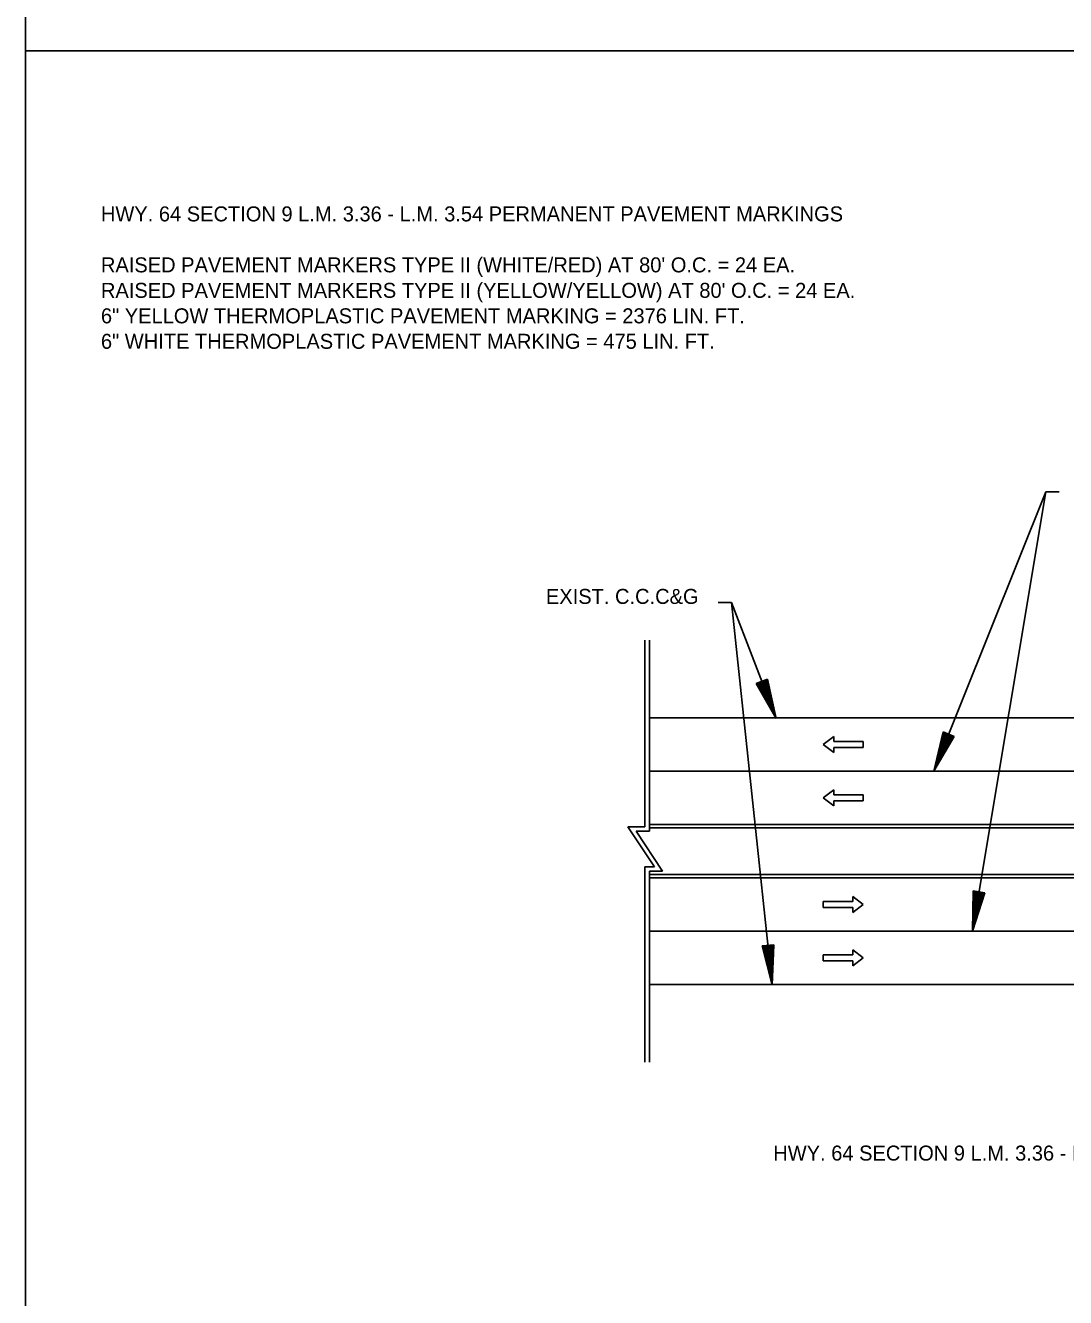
# Model space of a CAD drawing. Extents: x 1373096 to 1373266, y 381130 to 381790.
# Drawn here: x 1373096 to 1373174, y 381366.6 to 381462.1 of the extents above; entities that cross this region are included whole.
import ezdxf

# ---------------------------------------------------------------- set-up
doc = ezdxf.new("R2010")
doc.units = 0
for name, color, linetype in [('Default', 7, 'Continuous'), ('DSN_DRFT_Junk-No-Plot', 7, 'Continuous'), ('R_Draft', 7, 'Continuous')]:
    doc.layers.add(name, color=color, linetype=linetype)

msp = doc.modelspace()

# ---------------------------------------------------------------- linework, layer by layer
at = {"layer": 'Default'}
for p, q in [((1373172.526, 381427.08), (1373164.114, 381406.128)), ((1373172.526, 381427.08), (1373167.011, 381394.128)), ((1373173.526, 381427.08), (1373172.526, 381427.08)), ((1373147.952, 381418.797), (1373148.952, 381418.797)), ((1373148.952, 381418.797), (1373152.299, 381410.077)), ((1373148.952, 381418.797), (1373151.995, 381390.077)), ((1373142.445, 381415.965), (1373142.445, 381401.961)), ((1373142.778, 381415.965), (1373142.778, 381401.628)), ((1373151.644, 381413.039), (1373150.804, 381412.717)), ((1373150.804, 381412.717), (1373152.299, 381410.077)), ((1373150.874, 381412.743), (1373152.12, 381410.545)), ((1373150.946, 381412.771), (1373151.935, 381411.026)), ((1373151.016, 381412.798), (1373151.756, 381411.493)), ((1373151.087, 381412.825), (1373151.574, 381411.968)), ((1373151.158, 381412.853), (1373151.394, 381412.435)), ((1373151.29, 381412.903), (1373151.394, 381412.435)), ((1373151.36, 381412.93), (1373151.574, 381411.968)), ((1373151.433, 381412.958), (1373151.756, 381411.493)), ((1373151.503, 381412.985), (1373151.935, 381411.026)), ((1373151.574, 381413.012), (1373152.12, 381410.545)), ((1373151.644, 381413.039), (1373152.299, 381410.077)), ((1373156.607, 381408.728), (1373155.829, 381408.128)), ((1373156.607, 381408.728), (1373156.607, 381408.353)), ((1373164.814, 381409.08), (1373164.114, 381406.128)), ((1373165.65, 381408.744), (1373164.114, 381406.128)), ((1373164.884, 381409.052), (1373164.301, 381406.593)), ((1373165.58, 381408.772), (1373164.301, 381406.593)), ((1373164.955, 381409.023), (1373164.493, 381407.072)), ((1373165.509, 381408.801), (1373164.493, 381407.072)), ((1373165.025, 381408.995), (1373164.679, 381407.535)), ((1373165.439, 381408.829), (1373164.679, 381407.535)), ((1373165.65, 381408.744), (1373164.814, 381409.08)), ((1373165.096, 381408.967), (1373164.869, 381408.007)), ((1373165.367, 381408.858), (1373164.869, 381408.007)), ((1373165.167, 381408.938), (1373165.055, 381408.472)), ((1373165.297, 381408.886), (1373165.055, 381408.472)), ((1373155.829, 381408.128), (1373156.607, 381407.528)), ((1373156.607, 381408.353), (1373158.814, 381408.353)), ((1373156.607, 381407.903), (1373158.814, 381407.903)), ((1373156.607, 381407.903), (1373156.607, 381407.528)), ((1373158.814, 381408.353), (1373158.814, 381407.903)), ((1373156.607, 381404.728), (1373155.829, 381404.128)), ((1373155.829, 381404.128), (1373156.607, 381403.528)), ((1373156.607, 381404.728), (1373156.607, 381404.353)), ((1373156.607, 381404.353), (1373158.814, 381404.353)), ((1373158.814, 381404.353), (1373158.814, 381403.903)), ((1373156.607, 381403.903), (1373158.814, 381403.903)), ((1373156.607, 381403.903), (1373156.607, 381403.528)), ((1373143.155, 381398.961), (1373141.155, 381401.961)), ((1373142.445, 381401.961), (1373141.155, 381401.961)), ((1373142.778, 381401.628), (1373141.778, 381401.628)), ((1373143.778, 381398.628), (1373141.778, 381401.628)), ((1373142.445, 381398.961), (1373143.155, 381398.961)), ((1373142.445, 381384.291), (1373142.445, 381398.961)), ((1373142.778, 381384.291), (1373142.778, 381398.628)), ((1373142.778, 381398.628), (1373143.778, 381398.628)), ((1373158.035, 381396.353), (1373155.829, 381396.353)), ((1373155.829, 381396.353), (1373155.829, 381395.903)), ((1373158.035, 381396.728), (1373158.035, 381396.353)), ((1373158.035, 381396.728), (1373158.814, 381396.128)), ((1373167.062, 381397.161), (1373167.011, 381394.128)), ((1373167.95, 381397.012), (1373167.011, 381394.128)), ((1373167.95, 381397.012), (1373167.062, 381397.161)), ((1373167.136, 381397.149), (1373167.093, 381394.622)), ((1373167.876, 381397.025), (1373167.093, 381394.622)), ((1373167.211, 381397.136), (1373167.179, 381395.131)), ((1373167.8, 381397.037), (1373167.179, 381395.131)), ((1373167.285, 381397.124), (1373167.261, 381395.624)), ((1373167.726, 381397.05), (1373167.261, 381395.624)), ((1373167.361, 381397.111), (1373167.345, 381396.125)), ((1373167.649, 381397.063), (1373167.345, 381396.125)), ((1373167.436, 381397.098), (1373167.428, 381396.619)), ((1373167.575, 381397.075), (1373167.428, 381396.619)), ((1373158.035, 381395.903), (1373155.829, 381395.903)), ((1373158.814, 381396.128), (1373158.035, 381395.528)), ((1373158.035, 381395.903), (1373158.035, 381395.528)), ((1373152.126, 381393.108), (1373151.231, 381393.013)), ((1373151.231, 381393.013), (1373151.995, 381390.077)), ((1373151.306, 381393.021), (1373151.942, 381390.575)), ((1373151.382, 381393.029), (1373151.888, 381391.088)), ((1373151.456, 381393.037), (1373151.835, 381391.585)), ((1373151.532, 381393.045), (1373151.781, 381392.091)), ((1373151.609, 381393.053), (1373151.729, 381392.589)), ((1373151.749, 381393.068), (1373151.729, 381392.589)), ((1373151.823, 381393.076), (1373151.781, 381392.091)), ((1373151.901, 381393.084), (1373151.835, 381391.585)), ((1373151.975, 381393.092), (1373151.888, 381391.088)), ((1373152.052, 381393.1), (1373151.942, 381390.575)), ((1373152.126, 381393.108), (1373151.995, 381390.077)), ((1373158.035, 381392.728), (1373158.035, 381392.353)), ((1373158.035, 381392.728), (1373158.814, 381392.128)), ((1373158.035, 381392.353), (1373155.829, 381392.353)), ((1373155.829, 381392.353), (1373155.829, 381391.903)), ((1373158.035, 381391.903), (1373155.829, 381391.903)), ((1373158.814, 381392.128), (1373158.035, 381391.528)), ((1373158.035, 381391.903), (1373158.035, 381391.528))]:
    msp.add_line(p, q, dxfattribs=at)
for points in [[(1373095.974, 381570.174), (1373095.974, 381460.174), (1373265.974, 381460.174), (1373265.974, 381570.174)], [(1373095.974, 381460.174), (1373095.974, 381350.174), (1373265.974, 381350.174), (1373265.974, 381460.174)]]:
    msp.add_lwpolyline(points, close=True, dxfattribs=at)
at = {"layer": 'DSN_DRFT_Junk-No-Plot'}
for points in [[(1373095.974, 381570.174), (1373265.974, 381570.174), (1373265.974, 381460.174), (1373095.974, 381460.174)], [(1373095.974, 381570.174), (1373095.974, 381460.174), (1373265.974, 381460.174), (1373265.974, 381570.174)], [(1373095.974, 381460.174), (1373265.974, 381460.174), (1373265.974, 381350.174), (1373095.974, 381350.174)], [(1373095.974, 381460.174), (1373095.974, 381350.174), (1373265.974, 381350.174), (1373265.974, 381460.174)]]:
    msp.add_lwpolyline(points, close=True, dxfattribs=at)
at = {"layer": 'R_Draft'}
for p, q in [((1373142.778, 381410.128), (1373219.169, 381410.128)), ((1373142.778, 381406.128), (1373219.169, 381406.128)), ((1373142.778, 381402.128), (1373219.169, 381402.128)), ((1373142.778, 381401.878), (1373219.169, 381401.878)), ((1373142.778, 381398.378), (1373219.169, 381398.378)), ((1373142.778, 381398.128), (1373219.169, 381398.128)), ((1373142.778, 381394.128), (1373219.169, 381394.128)), ((1373142.778, 381390.128), (1373219.169, 381390.128))]:
    msp.add_line(p, q, dxfattribs=at)

# ---------------------------------------------------------------- texts
at = {"layer": 'Default'}
for s, p in [('HWY. 64 SECTION 9 L.M. 3.36 - L.M. 3.54 PERMANENT PAVEMENT MARKINGS', (1373101.637, 381447.385)), ("RAISED PAVEMENT MARKERS TYPE II (WHITE/RED) AT 80' O.C. = 24 EA.", (1373101.637, 381443.561)), ("RAISED PAVEMENT MARKERS TYPE II (YELLOW/YELLOW) AT 80' O.C. = 24 EA.", (1373101.637, 381441.649)), ('6" YELLOW THERMOPLASTIC PAVEMENT MARKING = 2376 LIN. FT.', (1373101.637, 381439.736)), ('6" WHITE THERMOPLASTIC PAVEMENT MARKING = 475 LIN. FT.', (1373101.637, 381437.824)), ('EXIST. C.C.C&G', (1373135.021, 381418.682))]:
    msp.add_text(s, height=1.125, dxfattribs=at).set_placement(p)
at = {"layer": 'R_Draft'}
msp.add_text('HWY. 64 SECTION 9 L.M. 3.36 - L.M. 3.54 PERMANENT PAVEMENT MARKINGS', height=1.125, dxfattribs=at).set_placement((1373152.078, 381376.91))

doc.saveas('drawing.dxf')
